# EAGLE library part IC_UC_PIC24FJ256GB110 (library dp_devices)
16-bit Flash Microcontroller with USB OTG
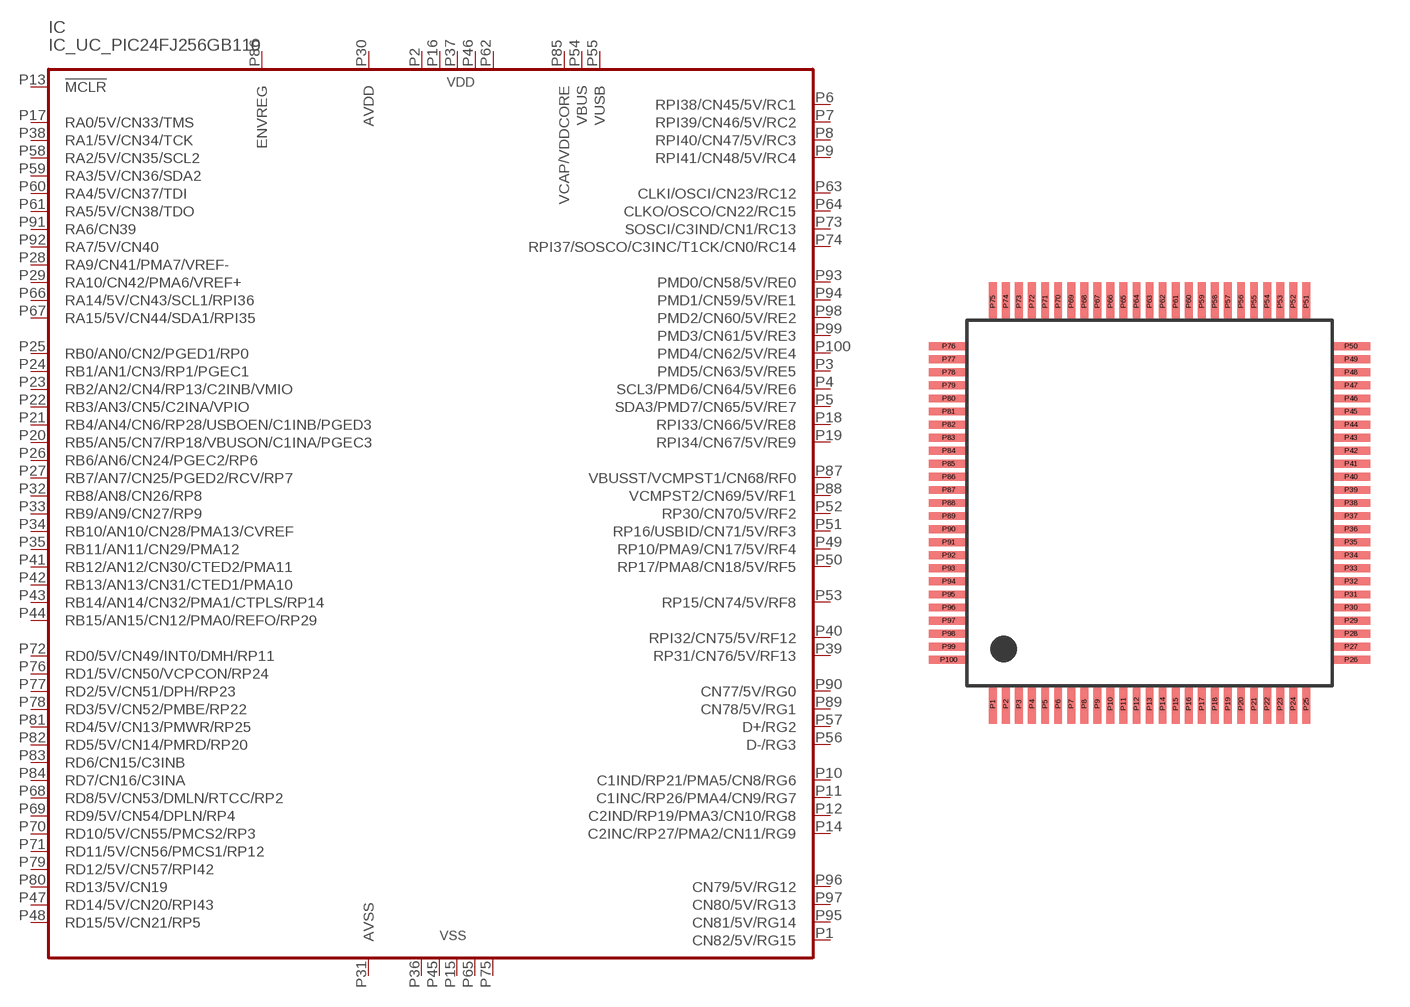
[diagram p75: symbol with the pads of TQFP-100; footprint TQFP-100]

Designator prefix IC

## IC_UC_PIC24FJ256GB110-TQFP100  [TQFP-100]
P1  CN82/5V/RG15
P2  VDD  pwr
P3  PMD5/CN63/5V/RE5
P4  SCL3/PMD6/CN64/5V/RE6
P5  SDA3/PMD7/CN65/5V/RE7
P6  RPI38/CN45/5V/RC1
P7  RPI39/CN46/5V/RC2
P8  RPI40/CN47/5V/RC3
P9  RPI41/CN48/5V/RC4
P10  C1IND/RP21/PMA5/CN8/RG6
P11  C1INC/RP26/PMA4/CN9/RG7
P12  C2IND/RP19/PMA3/CN10/RG8
P13  !MCLR  in
P14  C2INC/RP27/PMA2/CN11/RG9
P15  VSS  pwr
P16  VDD  pwr
P17  RA0/5V/CN33/TMS
P18  RPI33/CN66/5V/RE8
P19  RPI34/CN67/5V/RE9
P20  RB5/AN5/CN7/RP18/VBUSON/C1INA/PGEC3
P21  RB4/AN4/CN6/RP28/USBOEN/C1INB/PGED3
P22  RB3/AN3/CN5/C2INA/VPIO
P23  RB2/AN2/CN4/RP13/C2INB/VMIO
P24  RB1/AN1/CN3/RP1/PGEC1
P25  RB0/AN0/CN2/PGED1/RP0
P26  RB6/AN6/CN24/PGEC2/RP6
P27  RB7/AN7/CN25/PGED2/RCV/RP7
P28  RA9/CN41/PMA7/VREF-
P29  RA10/CN42/PMA6/VREF+
P30  AVDD  pwr
P31  AVSS  pwr
P32  RB8/AN8/CN26/RP8
P33  RB9/AN9/CN27/RP9
P34  RB10/AN10/CN28/PMA13/CVREF
P35  RB11/AN11/CN29/PMA12
P36  VSS  pwr
P37  VDD  pwr
P38  RA1/5V/CN34/TCK
P39  RP31/CN76/5V/RF13
P40  RPI32/CN75/5V/RF12
P41  RB12/AN12/CN30/CTED2/PMA11
P42  RB13/AN13/CN31/CTED1/PMA10
P43  RB14/AN14/CN32/PMA1/CTPLS/RP14
P44  RB15/AN15/CN12/PMA0/REFO/RP29
P45  VSS  pwr
P46  VDD  pwr
P47  RD14/5V/CN20/RPI43
P48  RD15/5V/CN21/RP5
P49  RP10/PMA9/CN17/5V/RF4
P50  RP17/PMA8/CN18/5V/RF5
P51  RP16/USBID/CN71/5V/RF3
P52  RP30/CN70/5V/RF2
P53  RP15/CN74/5V/RF8
P54  VBUS  pwr
P55  VUSB  pwr
P56  D-/RG3
P57  D+/RG2
P58  RA2/5V/CN35/SCL2
P59  RA3/5V/CN36/SDA2
P60  RA4/5V/CN37/TDI
P61  RA5/5V/CN38/TDO
P62  VDD  pwr
P63  CLKI/OSCI/CN23/RC12
P64  CLKO/OSCO/CN22/RC15
P65  VSS  pwr
P66  RA14/5V/CN43/SCL1/RPI36
P67  RA15/5V/CN44/SDA1/RPI35
P68  RD8/5V/CN53/DMLN/RTCC/RP2
P69  RD9/5V/CN54/DPLN/RP4
P70  RD10/5V/CN55/PMCS2/RP3
P71  RD11/5V/CN56/PMCS1/RP12
P72  RD0/5V/CN49/INT0/DMH/RP11
P73  SOSCI/C3IND/CN1/RC13
P74  RPI37/SOSCO/C3INC/T1CK/CN0/RC14
P75  VSS  pwr
P76  RD1/5V/CN50/VCPCON/RP24
P77  RD2/5V/CN51/DPH/RP23
P78  RD3/5V/CN52/PMBE/RP22
P79  RD12/5V/CN57/RPI42
P80  RD13/5V/CN19
P81  RD4/5V/CN13/PMWR/RP25
P82  RD5/5V/CN14/PMRD/RP20
P83  RD6/CN15/C3INB
P84  RD7/CN16/C3INA
P85  VCAP/VDDCORE  pwr
P86  ENVREG  in
P87  VBUSST/VCMPST1/CN68/RF0
P88  VCMPST2/CN69/5V/RF1
P89  CN78/5V/RG1
P90  CN77/5V/RG0
P91  RA6/CN39
P92  RA7/5V/CN40
P93  PMD0/CN58/5V/RE0
P94  PMD1/CN59/5V/RE1
P95  CN81/5V/RG14
P96  CN79/5V/RG12
P97  CN80/5V/RG13
P98  PMD2/CN60/5V/RE2
P99  PMD3/CN61/5V/RE3
P100  PMD4/CN62/5V/RE4

## Footprint TQFP-100 (pad centres in mm)
100-Lead Plastic Thin Quad Flatpack
smd 0.3 x 1.5: P1 -6,-7.7; P2 -5.5,-7.7; P3 -5,-7.7; P4 -4.5,-7.7; P5 -4,-7.7; P6 -3.5,-7.7; P7 -3,-7.7; P8 -2.5,-7.7; P9 -2,-7.7; P10 -1.5,-7.7; P11 -1,-7.7; P12 -0.5,-7.7; P13 0,-7.7; P14 0.5,-7.7; P15 1,-7.7; P16 1.5,-7.7; P17 2,-7.7; P18 2.5,-7.7; P19 3,-7.7; P20 3.5,-7.7; P21 4,-7.7; P22 4.5,-7.7; P23 5,-7.7; P24 5.5,-7.7; P25 6,-7.7; P51 6,7.7; P52 5.5,7.7; P53 5,7.7; P54 4.5,7.7; P55 4,7.7; P56 3.5,7.7; P57 3,7.7; P58 2.5,7.7; P59 2,7.7; P60 1.5,7.7; P61 1,7.7; P62 0.5,7.7; P63 0,7.7; P64 -0.5,7.7; P65 -1,7.7; P66 -1.5,7.7; P67 -2,7.7; P68 -2.5,7.7; P69 -3,7.7; P70 -3.5,7.7; P71 -4,7.7; P72 -4.5,7.7; P73 -5,7.7; P74 -5.5,7.7; P75 -6,7.7
smd 1.5 x 0.3: P26 7.7,-6; P27 7.7,-5.5; P28 7.7,-5; P29 7.7,-4.5; P30 7.7,-4; P31 7.7,-3.5; P32 7.7,-3; P33 7.7,-2.5; P34 7.7,-2; P35 7.7,-1.5; P36 7.7,-1; P37 7.7,-0.5; P38 7.7,0; P39 7.7,0.5; P40 7.7,1; P41 7.7,1.5; P42 7.7,2; P43 7.7,2.5; P44 7.7,3; P45 7.7,3.5; P46 7.7,4; P47 7.7,4.5; P48 7.7,5; P49 7.7,5.5; P50 7.7,6; P76 -7.7,6; P77 -7.7,5.5; P78 -7.7,5; P79 -7.7,4.5; P80 -7.7,4; P81 -7.7,3.5; P82 -7.7,3; P83 -7.7,2.5; P84 -7.7,2; P85 -7.7,1.5; P86 -7.7,1; P87 -7.7,0.5; P88 -7.7,0; P89 -7.7,-0.5; P90 -7.7,-1; P91 -7.7,-1.5; P92 -7.7,-2; P93 -7.7,-2.5; P94 -7.7,-3; P95 -7.7,-3.5; P96 -7.7,-4; P97 -7.7,-4.5; P98 -7.7,-5; P99 -7.7,-5.5; P100 -7.7,-6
